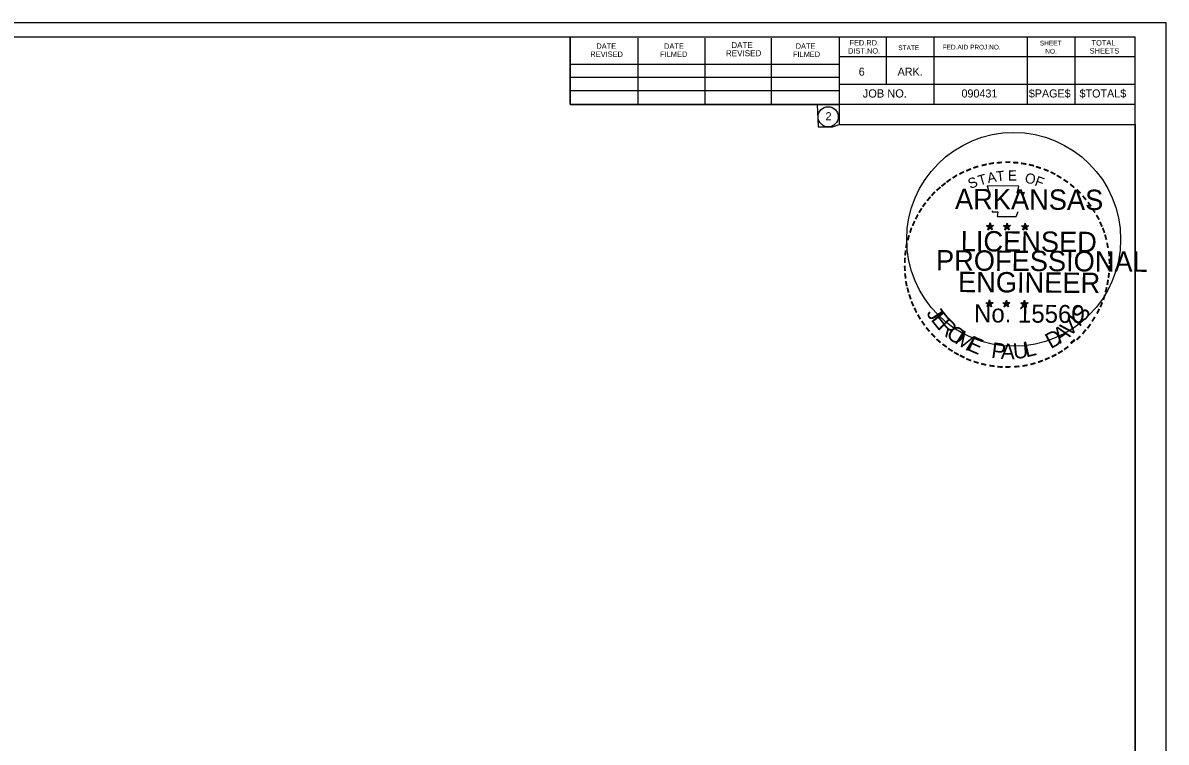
# Model space of a CAD drawing. Extents: x -1.3 to 32.1, y -0.2 to 20.7.
# Drawn here: x 15.42 to 32.07, y 10.27 to 20.75 of the extents above; entities that cross this region are included whole.
import ezdxf

# ---------------------------------------------------------------- set-up
doc = ezdxf.new("R2010")
doc.units = 0
for name, color, linetype in [('Level 1', 7, 'Continuous'), ('Level 49', 7, 'Continuous'), ('Level 62', 7, 'Continuous'), ('Level 63', 7, 'Continuous'), ('Stamp Mask', 7, 'Continuous')]:
    doc.layers.add(name, color=color, linetype=linetype)

msp = doc.modelspace()

# ---------------------------------------------------------------- linework, layer by layer
at = {"layer": 'Level 1'}
for p, q in [((-0.001, 20.545), (31.617, 20.545)), ((23.391, 19.557), (23.391, 20.545)), ((24.377, 19.557), (24.377, 20.525)), ((25.353, 19.557), (25.353, 20.525)), ((26.321, 19.557), (26.321, 20.525)), ((27.307, 20.545), (27.307, 19.265)), ((27.991, 20.545), (27.991, 19.851)), ((28.685, 20.545), (28.685, 19.557)), ((30.043, 20.545), (30.043, 19.557)), ((30.737, 20.545), (30.737, 19.557)), ((31.617, -0.001), (31.617, 20.545)), ((23.391, 20.143), (27.307, 20.143)), ((31.617, 20.251), (27.307, 20.251)), ((31.617, 20.253), (31.617, 20.253)), ((23.391, 19.957), (27.307, 19.957)), ((31.617, 19.851), (27.307, 19.851)), ((23.391, 19.557), (23.391, 19.763)), ((23.391, 19.763), (27.307, 19.763)), ((31.617, 19.557), (23.391, 19.557)), ((27.307, 19.557), (27.307, 19.274)), ((27.307, 19.265), (31.617, 19.265))]:
    msp.add_line(p, q, dxfattribs=at)
msp.add_lwpolyline([(-0.001, 20.545), (23.391, 20.545), (23.391, 19.557), (27.307, 19.557), (27.307, 19.265), (31.617, 19.265), (31.617, 8.293), (-0.001, 8.293)], close=True, dxfattribs=at)
msp.add_circle((27.146, 19.379), 0.147, dxfattribs=at)
at = {"layer": 'Level 49'}
for p, q in [((29.504, 17.836), (29.497, 17.795)), ((29.504, 17.836), (29.497, 17.799)), ((29.504, 17.836), (29.5, 17.799)), ((29.504, 17.779), (29.504, 17.836)), ((29.504, 17.836), (29.513, 17.795)), ((29.504, 17.836), (29.511, 17.799)), ((29.504, 17.836), (29.506, 17.799)), ((29.751, 17.832), (29.744, 17.794)), ((29.751, 17.832), (29.744, 17.795)), ((29.751, 17.832), (29.745, 17.795)), ((29.751, 17.779), (29.751, 17.832)), ((29.751, 17.832), (29.76, 17.794)), ((29.751, 17.832), (29.758, 17.795)), ((29.751, 17.832), (29.753, 17.795)), ((30.012, 17.828), (30.003, 17.794)), ((30.012, 17.828), (30.009, 17.792)), ((30.012, 17.828), (30.009, 17.792)), ((30.012, 17.773), (30.012, 17.828)), ((30.012, 17.828), (30.023, 17.792)), ((30.012, 17.828), (30.02, 17.792)), ((30.012, 17.828), (30.016, 17.792)), ((29.451, 17.795), (29.504, 17.779)), ((29.451, 17.795), (29.489, 17.794)), ((29.451, 17.795), (29.489, 17.792)), ((29.451, 17.795), (29.486, 17.786)), ((29.451, 17.795), (29.486, 17.781)), ((29.451, 17.795), (29.486, 17.779)), ((29.451, 17.795), (29.486, 17.773)), ((29.473, 17.735), (29.504, 17.779)), ((29.473, 17.735), (29.486, 17.777)), ((29.473, 17.735), (29.489, 17.772)), ((29.473, 17.735), (29.491, 17.77)), ((29.473, 17.735), (29.497, 17.766)), ((29.473, 17.735), (29.504, 17.766)), ((29.473, 17.735), (29.504, 17.762)), ((29.555, 17.795), (29.504, 17.779)), ((29.535, 17.733), (29.504, 17.779)), ((29.535, 17.733), (29.504, 17.766)), ((29.535, 17.733), (29.504, 17.762)), ((29.555, 17.795), (29.508, 17.792)), ((29.535, 17.733), (29.508, 17.766)), ((29.555, 17.795), (29.513, 17.788)), ((29.555, 17.795), (29.513, 17.784)), ((29.535, 17.733), (29.513, 17.777)), ((29.535, 17.733), (29.513, 17.772)), ((29.535, 17.733), (29.519, 17.779)), ((29.555, 17.795), (29.52, 17.784)), ((29.555, 17.795), (29.526, 17.781)), ((29.555, 17.795), (29.528, 17.779)), ((29.698, 17.794), (29.751, 17.779)), ((29.698, 17.794), (29.736, 17.792)), ((29.698, 17.794), (29.736, 17.788)), ((29.698, 17.794), (29.736, 17.786)), ((29.698, 17.794), (29.734, 17.779)), ((29.698, 17.794), (29.734, 17.777)), ((29.698, 17.794), (29.734, 17.772)), ((29.72, 17.733), (29.751, 17.779)), ((29.72, 17.733), (29.736, 17.773)), ((29.72, 17.733), (29.736, 17.772)), ((29.72, 17.733), (29.738, 17.77)), ((29.72, 17.733), (29.744, 17.764)), ((29.72, 17.733), (29.751, 17.764)), ((29.72, 17.733), (29.751, 17.762)), ((29.802, 17.794), (29.751, 17.779)), ((29.782, 17.733), (29.751, 17.779)), ((29.782, 17.733), (29.751, 17.764)), ((29.782, 17.733), (29.751, 17.762)), ((29.802, 17.794), (29.756, 17.792)), ((29.782, 17.733), (29.756, 17.764)), ((29.802, 17.794), (29.76, 17.786)), ((29.802, 17.794), (29.76, 17.784)), ((29.782, 17.733), (29.76, 17.777)), ((29.782, 17.733), (29.76, 17.77)), ((29.782, 17.733), (29.766, 17.777)), ((29.802, 17.794), (29.767, 17.781)), ((29.802, 17.794), (29.773, 17.779)), ((29.802, 17.794), (29.775, 17.777)), ((29.959, 17.792), (30.012, 17.773)), ((29.959, 17.792), (30.002, 17.786)), ((29.959, 17.792), (29.998, 17.784)), ((29.959, 17.792), (29.998, 17.781)), ((29.959, 17.792), (29.996, 17.777)), ((29.959, 17.792), (29.996, 17.772)), ((29.959, 17.792), (29.996, 17.772)), ((29.98, 17.731), (30.012, 17.773)), ((29.98, 17.731), (29.998, 17.772)), ((29.98, 17.731), (30.002, 17.766)), ((29.98, 17.731), (30.002, 17.764)), ((29.98, 17.731), (30.012, 17.764)), ((29.98, 17.731), (30.009, 17.762)), ((29.98, 17.731), (30.016, 17.757)), ((30.064, 17.792), (30.012, 17.773)), ((30.042, 17.731), (30.012, 17.773)), ((30.042, 17.731), (30.012, 17.764)), ((30.042, 17.731), (30.012, 17.757)), ((30.064, 17.792), (30.018, 17.786)), ((30.042, 17.731), (30.018, 17.762)), ((30.064, 17.792), (30.023, 17.784)), ((30.064, 17.792), (30.023, 17.779)), ((30.042, 17.731), (30.023, 17.772)), ((30.042, 17.731), (30.023, 17.766)), ((30.042, 17.731), (30.027, 17.772)), ((30.064, 17.792), (30.031, 17.777)), ((30.064, 17.792), (30.033, 17.777)), ((30.064, 17.792), (30.038, 17.773)), ((29.444, 16.672), (29.497, 16.656)), ((29.444, 16.672), (29.482, 16.67)), ((29.444, 16.672), (29.48, 16.665)), ((29.444, 16.672), (29.48, 16.665)), ((29.444, 16.672), (29.48, 16.657)), ((29.444, 16.672), (29.48, 16.656)), ((29.444, 16.672), (29.48, 16.654)), ((29.462, 16.615), (29.497, 16.656)), ((29.462, 16.615), (29.48, 16.656)), ((29.462, 16.615), (29.482, 16.648)), ((29.462, 16.615), (29.484, 16.648)), ((29.497, 16.712), (29.486, 16.676)), ((29.497, 16.712), (29.489, 16.672)), ((29.497, 16.712), (29.491, 16.672)), ((29.497, 16.656), (29.497, 16.712)), ((29.497, 16.712), (29.504, 16.672)), ((29.497, 16.712), (29.504, 16.672)), ((29.497, 16.712), (29.497, 16.672)), ((29.548, 16.672), (29.497, 16.656)), ((29.526, 16.612), (29.497, 16.656)), ((29.548, 16.672), (29.5, 16.67)), ((29.548, 16.672), (29.504, 16.665)), ((29.548, 16.672), (29.504, 16.663)), ((29.526, 16.612), (29.504, 16.656)), ((29.526, 16.612), (29.504, 16.648)), ((29.548, 16.672), (29.511, 16.661)), ((29.526, 16.612), (29.511, 16.656)), ((29.548, 16.672), (29.515, 16.657)), ((29.548, 16.672), (29.519, 16.656)), ((29.691, 16.672), (29.744, 16.656)), ((29.691, 16.672), (29.729, 16.668)), ((29.691, 16.672), (29.729, 16.665)), ((29.691, 16.672), (29.729, 16.663)), ((29.691, 16.672), (29.727, 16.657)), ((29.691, 16.672), (29.727, 16.654)), ((29.691, 16.672), (29.727, 16.65)), ((29.709, 16.612), (29.744, 16.656)), ((29.709, 16.612), (29.729, 16.654)), ((29.744, 16.709), (29.734, 16.672)), ((29.744, 16.709), (29.736, 16.672)), ((29.744, 16.709), (29.738, 16.672)), ((29.744, 16.656), (29.744, 16.709)), ((29.744, 16.709), (29.751, 16.67)), ((29.744, 16.709), (29.751, 16.67)), ((29.744, 16.709), (29.744, 16.672)), ((29.793, 16.67), (29.744, 16.656)), ((29.773, 16.612), (29.744, 16.656)), ((29.793, 16.67), (29.749, 16.67)), ((29.793, 16.67), (29.751, 16.663)), ((29.793, 16.67), (29.751, 16.663)), ((29.773, 16.612), (29.751, 16.654)), ((29.773, 16.612), (29.751, 16.648)), ((29.793, 16.67), (29.758, 16.657)), ((29.773, 16.612), (29.758, 16.654)), ((29.793, 16.67), (29.764, 16.656)), ((29.793, 16.67), (29.766, 16.654)), ((29.952, 16.668), (30.005, 16.65)), ((29.952, 16.668), (29.991, 16.665)), ((29.952, 16.668), (29.991, 16.661)), ((29.952, 16.668), (29.989, 16.657)), ((29.952, 16.668), (29.989, 16.654)), ((29.952, 16.668), (29.987, 16.65)), ((29.952, 16.668), (29.987, 16.646)), ((29.972, 16.608), (30.005, 16.65)), ((29.972, 16.608), (29.989, 16.65)), ((30.005, 16.707), (29.996, 16.668)), ((30.005, 16.707), (29.998, 16.668)), ((30.005, 16.707), (30.002, 16.668)), ((30.005, 16.65), (30.005, 16.707)), ((30.005, 16.707), (30.012, 16.668)), ((30.005, 16.707), (30.012, 16.668)), ((30.005, 16.707), (30.005, 16.668)), ((30.056, 16.668), (30.005, 16.65)), ((30.034, 16.608), (30.005, 16.65)), ((30.056, 16.668), (30.011, 16.665)), ((30.056, 16.668), (30.012, 16.661)), ((30.056, 16.668), (30.012, 16.657)), ((30.034, 16.608), (30.016, 16.65)), ((30.034, 16.608), (30.018, 16.65)), ((30.056, 16.668), (30.023, 16.656)), ((30.056, 16.668), (30.025, 16.65)), ((30.056, 16.668), (30.027, 16.65)), ((29.462, 16.615), (29.497, 16.646)), ((29.462, 16.615), (29.489, 16.643)), ((29.462, 16.615), (29.497, 16.641)), ((29.526, 16.612), (29.493, 16.641)), ((29.526, 16.612), (29.497, 16.643)), ((29.526, 16.612), (29.498, 16.643)), ((29.709, 16.612), (29.729, 16.646)), ((29.709, 16.612), (29.731, 16.646)), ((29.709, 16.612), (29.736, 16.643)), ((29.709, 16.612), (29.744, 16.643)), ((29.709, 16.612), (29.744, 16.639)), ((29.773, 16.612), (29.742, 16.639)), ((29.773, 16.612), (29.744, 16.643)), ((29.773, 16.612), (29.745, 16.643)), ((29.972, 16.608), (29.991, 16.643)), ((29.972, 16.608), (29.994, 16.643)), ((29.972, 16.608), (29.998, 16.639)), ((29.972, 16.608), (30.003, 16.639)), ((29.972, 16.608), (30.005, 16.635)), ((30.034, 16.608), (30.003, 16.639)), ((30.034, 16.608), (30.003, 16.635)), ((30.034, 16.608), (30.009, 16.639)), ((30.034, 16.608), (30.012, 16.643))]:
    msp.add_line(p, q, dxfattribs=at)
for points in [[(29.462, 18.372), (29.498, 18.247)], [(29.981, 18.231), (30.003, 18.275), (29.899, 18.269), (29.923, 18.368), (29.462, 18.372)], [(29.533, 18.011), (29.533, 17.997), (29.616, 17.995), (29.608, 17.927), (29.884, 17.925), (29.914, 18.002)], [(29.504, 17.836), (29.535, 17.733), (29.451, 17.795), (29.555, 17.795), (29.473, 17.735), (29.504, 17.836)], [(29.751, 17.832), (29.782, 17.733), (29.698, 17.794), (29.802, 17.794), (29.72, 17.733), (29.751, 17.832)], [(30.012, 17.828), (30.042, 17.731), (29.959, 17.792), (30.064, 17.792), (29.98, 17.731), (30.012, 17.828)], [(29.497, 16.712), (29.526, 16.612), (29.444, 16.672), (29.548, 16.672), (29.462, 16.615), (29.497, 16.712)], [(29.744, 16.709), (29.773, 16.612), (29.691, 16.672), (29.793, 16.67), (29.709, 16.612), (29.744, 16.709)], [(30.005, 16.707), (30.034, 16.608), (29.952, 16.668), (30.056, 16.668), (29.972, 16.608), (30.005, 16.707)], [(30.691, 16.074), (30.684, 16.098), (30.728, 16.134)], [(30.724, 16.14), (30.731, 16.118), (30.688, 16.079)], [(30.731, 16.121), (30.688, 16.083)], [(30.731, 16.118), (30.689, 16.081)]]:
    msp.add_lwpolyline(points, dxfattribs=at)
for centre, radius in [((29.505, 17.778), 0.0255), ((29.505, 17.778), 0.0231), ((29.505, 17.778), 0.0214), ((29.505, 17.778), 0.0197), ((29.505, 17.778), 0.0172), ((29.505, 17.778), 0.0159), ((29.505, 17.778), 0.0147), ((29.505, 17.778), 0.0126), ((29.505, 17.778), 0.0111), ((29.505, 17.778), 0.00921), ((29.505, 17.778), 0.00734), ((29.505, 17.778), 0.00548), ((29.505, 17.778), 0.00439), ((29.505, 17.778), 0.00214), ((29.752, 17.776), 0.0255), ((29.752, 17.776), 0.0231), ((29.752, 17.776), 0.0214), ((29.752, 17.776), 0.0197), ((29.752, 17.776), 0.0172), ((29.752, 17.776), 0.0159), ((29.752, 17.776), 0.0147), ((29.752, 17.776), 0.0126), ((29.752, 17.776), 0.0111), ((29.752, 17.776), 0.00921), ((29.752, 17.776), 0.00734), ((29.752, 17.776), 0.00548), ((29.752, 17.776), 0.00439), ((29.752, 17.776), 0.00214), ((30.014, 17.773), 0.0255), ((30.014, 17.773), 0.0231), ((30.014, 17.773), 0.0214), ((30.014, 17.773), 0.0197), ((30.014, 17.773), 0.0172), ((30.014, 17.773), 0.0159), ((30.014, 17.773), 0.0147), ((30.014, 17.773), 0.0126), ((30.014, 17.773), 0.0111), ((30.014, 17.773), 0.00921), ((30.014, 17.773), 0.00734), ((30.014, 17.773), 0.00548), ((30.014, 17.773), 0.00439), ((30.014, 17.773), 0.00214), ((29.496, 16.656), 0.0255), ((29.496, 16.656), 0.0231), ((29.496, 16.656), 0.0214), ((29.496, 16.656), 0.0197), ((29.496, 16.656), 0.0172), ((29.496, 16.656), 0.0159), ((29.496, 16.656), 0.0147), ((29.496, 16.656), 0.0126), ((29.496, 16.656), 0.0111), ((29.496, 16.656), 0.00921), ((29.496, 16.656), 0.00734), ((29.496, 16.656), 0.00548), ((29.496, 16.656), 0.00439), ((29.496, 16.656), 0.00214), ((29.744, 16.654), 0.0255), ((29.744, 16.654), 0.0231), ((29.744, 16.654), 0.0214), ((29.744, 16.654), 0.0197), ((29.744, 16.654), 0.0172), ((29.744, 16.654), 0.0159), ((29.744, 16.654), 0.0147), ((29.744, 16.654), 0.0126), ((29.744, 16.654), 0.0111), ((29.744, 16.654), 0.00921), ((29.744, 16.654), 0.00734), ((29.744, 16.654), 0.00548), ((29.744, 16.654), 0.00439), ((29.744, 16.654), 0.00214), ((30.006, 16.65), 0.0255), ((30.006, 16.65), 0.0231), ((30.006, 16.65), 0.0214), ((30.006, 16.65), 0.0197), ((30.006, 16.65), 0.0172), ((30.006, 16.65), 0.0159), ((30.006, 16.65), 0.0147), ((30.006, 16.65), 0.0126), ((30.006, 16.65), 0.0111), ((30.006, 16.65), 0.00921), ((30.006, 16.65), 0.00734), ((30.006, 16.65), 0.00548), ((30.006, 16.65), 0.00439), ((30.006, 16.65), 0.00214)]:
    msp.add_circle(centre, radius, dxfattribs=at)
at = {"layer": 'Level 62'}
msp.add_lwpolyline([(-0.001, 20.545), (23.391, 20.545), (23.391, 20.545), (23.391, 19.557), (23.391, 19.557), (26.987, 19.557), (26.999, 19.232), (27.211, 19.232), (27.307, 19.265), (31.617, 19.265), (31.617, 8.293), (-0.001, 8.293)], close=True, dxfattribs=at)
at = {"layer": 'Level 63'}
msp.add_lwpolyline([(-1.263, -0.2), (32.067, -0.2), (32.067, 20.746), (-1.263, 20.746)], close=True, dxfattribs=at)
at = {"layer": 'Stamp Mask'}
msp.add_circle((29.847, 17.594), 1.557, dxfattribs=at)

# ---------------------------------------------------------------- texts
at = {"layer": 'Level 1'}
for s, height, p in [('FED.RD.', 0.0782, (27.455, 20.417)), ('SHEET', 0.0684, (30.229, 20.417)), ('TOTAL', 0.0782, (30.981, 20.417)), ('REVISED', 0.0782, (23.683, 20.251)), ('DATE', 0.0782, (23.771, 20.369)), ('FILMED', 0.0782, (24.699, 20.251)), ('DATE', 0.0782, (24.757, 20.369)), ('REVISED', 0.0879, (25.657, 20.261)), ('DATE', 0.0879, (25.735, 20.379)), ('FILMED', 0.0782, (26.633, 20.251)), ('DATE', 0.0782, (26.673, 20.369)), ('DIST.NO.', 0.0782, (27.435, 20.299)), ('STATE', 0.0684, (28.167, 20.349)), ('FED.AID PROJ.NO.', 0.0684, (28.813, 20.359)), ('NO.', 0.0684, (30.307, 20.299)), ('SHEETS', 0.0782, (30.953, 20.299)), ('6', 0.117, (27.591, 19.977)), ('ARK.', 0.1172, (28.157, 19.977)), ('JOB NO.', 0.12, (27.65, 19.659)), ('090431', 0.1172, (29.087, 19.66)), ('$PAGE$', 0.1172, (30.067, 19.66)), ('$TOTAL$', 0.1172, (30.806, 19.66)), ('2', 0.117, (27.108, 19.329))]:
    msp.add_text(s, height=height, dxfattribs=at).set_placement(p)
at = {"layer": 'Level 49'}
for s, height, rotation, p in [('-', 0.237, 18.7785, (29.275, 18.542)), ('-', 0.237, 13.2325, (29.387, 18.577)), ('-', 0.237, 9.8217, (29.486, 18.6)), ('-', 0.237, 5.4992, (29.595, 18.615)), ('-', 0.237, 359.7886, (29.709, 18.626)), ('-', 0.237, 357.3454, (29.819, 18.622)), ('-', 0.237, 351.7641, (29.927, 18.613)), ('-', 0.237, 346.8073, (30.034, 18.597)), ('-', 0.237, 341.9386, (30.128, 18.571)), ('-', 0.237, 35.8341, (28.911, 18.344)), ('-', 0.237, 33.666, (28.997, 18.403)), ('-', 0.237, 28.3942, (29.087, 18.456)), ('-', 0.237, 23.9096, (29.18, 18.501)), ('S', 0.148, 21.1964, (29.215, 18.326)), ('T', 0.148, 16.006, (29.35, 18.375)), ('A', 0.148, 10.8156, (29.475, 18.412)), ('T', 0.148, 5.6252, (29.601, 18.436)), ('E', 0.148, 0.4347, (29.764, 18.45)), ('O', 0.148, 350.0539, (30.002, 18.419)), ('F', 0.148, 339.6731, (30.142, 18.383)), ('-', 0.237, 337.4575, (30.236, 18.538)), ('-', 0.237, 333.7235, (30.331, 18.5)), ('-', 0.237, 329.2433, (30.415, 18.456)), ('-', 0.237, 42.5646, (28.776, 18.227)), ('-', 0.237, 38.5531, (28.842, 18.287)), ('ARKANSAS', 0.2964, 359.6024, (28.992, 18.035)), ('-', 0.237, 325.4651, (30.51, 18.399)), ('-', 0.237, 320.1321, (30.6, 18.337)), ('-', 0.237, 315.181, (30.689, 18.264)), ('-', 0.237, 50.2166, (28.648, 18.086)), ('-', 0.237, 48.0254, (28.708, 18.158)), ('-', 0.237, 309.4821, (30.772, 18.181)), ('-', 0.237, 57.673, (28.538, 17.922)), ('-', 0.237, 53.8349, (28.586, 18.002)), ('-', 0.237, 306.2546, (30.847, 18.092)), ('-', 0.207, 303.2777, (30.92, 18.006)), ('-', 0.237, 67.3767, (28.454, 17.742)), ('-', 0.237, 62.4737, (28.492, 17.832)), ('-', 0.237, 299.2708, (30.966, 17.916)), ('-', 0.237, 294.2652, (31.013, 17.825)), ('-', 0.237, 75.0634, (28.39, 17.543)), ('-', 0.237, 71.9969, (28.419, 17.649)), ('LICENSED', 0.2964, 359.6024, (29.075, 17.421)), ('-', 0.237, 290.1752, (31.053, 17.742)), ('-', 0.237, 284.7257, (31.085, 17.654)), ('-', 0.237, 80.8037, (28.368, 17.439)), ('-', 0.237, 280.1517, (31.114, 17.543)), ('-', 0.237, 88.6646, (28.353, 17.232)), ('-', 0.237, 84.7887, (28.357, 17.336)), ('PROFESSIONAL', 0.29643, 359.6024, (28.715, 17.142)), ('-', 0.237, 276.1986, (31.139, 17.429)), ('-', 0.237, 273.9325, (31.147, 17.322)), ('-', 0.237, 93.7983, (28.357, 17.124)), ('-', 0.237, 269.5431, (31.15, 17.23)), ('-', 0.237, 98.5503, (28.368, 17.023)), ('-', 0.237, 101.3173, (28.384, 16.915)), ('ENGINEER', 0.2964, 359.6024, (29.036, 16.826)), ('-', 0.237, 260.5977, (31.134, 17.034)), ('-', 0.237, 263.1196, (31.147, 17.131)), ('-', 0.237, 105.0602, (28.41, 16.828)), ('-', 0.237, 255.365, (31.117, 16.934)), ('-', 0.237, 108.6898, (28.441, 16.736)), ('-', 0.237, 113.6667, (28.478, 16.645)), ('No. 15560', 0.2608, 359.6024, (29.27, 16.387)), ('-', 0.237, 247.4911, (31.059, 16.725)), ('-', 0.237, 252.4705, (31.092, 16.826)), ('-', 0.237, 115.3312, (28.523, 16.553)), ('-', 0.237, 120.0495, (28.575, 16.465)), ('J', 0.228, 303.9209, (28.568, 16.518)), ('E', 0.228, 308.618, (28.633, 16.423)), ('I', 0.228, 49.9999, (30.803, 16.307)), ('S', 0.228, 53.5227, (30.86, 16.373)), ('-', 0.237, 244.2221, (31.017, 16.634)), ('-', 0.237, 125.4958, (28.635, 16.383)), ('-', 0.237, 130.3205, (28.701, 16.301)), ('R', 0.228, 314.7784, (28.728, 16.306)), ('O', 0.228, 321.6761, (28.85, 16.188)), ('A', 0.228, 34.8903, (30.521, 16.069)), ('V', 0.228, 41.4844, (30.652, 16.164)), ('-', 0.237, 233.4476, (30.902, 16.427)), ('-', 0.237, 238.6736, (30.958, 16.524)), ('-', 0.237, 133.8262, (28.778, 16.22)), ('-', 0.237, 138.5362, (28.853, 16.151)), ('M', 0.228, 328.1357, (28.975, 16.092)), ('E', 0.228, 336.4966, (29.153, 15.989)), ('D', 0.228, 28.5809, (30.386, 15.994)), ('-', 0.237, 225.3677, (30.763, 16.26)), ('-', 0.237, 233.4476, (30.832, 16.346)), ('-', 0.237, 144.2487, (28.939, 16.09)), ('-', 0.237, 147.6922, (29.019, 16.034)), ('P', 0.228, 351.9783, (29.512, 15.872)), ('A', 0.228, 357.9896, (29.658, 15.853)), ('U', 0.228, 5.7635, (29.849, 15.851)), ('L', 0.228, 13.0992, (30.027, 15.874)), ('-', 0.237, 211.8515, (30.523, 16.059)), ('-', 0.237, 215.3387, (30.602, 16.116)), ('-', 0.237, 151.1728, (29.103, 15.986)), ('-', 0.237, 154.2026, (29.184, 15.948)), ('-', 0.237, 158.1636, (29.275, 15.907)), ('-', 0.237, 162.4007, (29.378, 15.876)), ('-', 0.237, 200.3208, (30.256, 15.922)), ('-', 0.237, 203.854, (30.347, 15.962)), ('-', 0.237, 206.9592, (30.441, 16.008)), ('-', 0.237, 167.1579, (29.482, 15.852)), ('-', 0.237, 172.7179, (29.595, 15.836)), ('-', 0.237, 176.1207, (29.707, 15.825)), ('-', 0.237, 181.1942, (29.817, 15.829)), ('-', 0.237, 185.4191, (29.937, 15.838)), ('-', 0.237, 190.8882, (30.047, 15.856)), ('-', 0.237, 195.0767, (30.155, 15.885))]:
    msp.add_text(s, height=height, rotation=rotation, dxfattribs=at).set_placement(p)

doc.saveas('drawing.dxf')
